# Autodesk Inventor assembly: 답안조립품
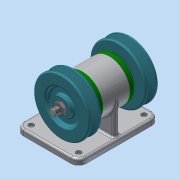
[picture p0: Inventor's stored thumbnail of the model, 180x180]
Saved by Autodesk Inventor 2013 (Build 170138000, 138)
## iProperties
Created: 2019-09
Part Number: 답안조립품
Document SubType Name: Assembly
Designer: Administrator
Author: Administrator
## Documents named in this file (10)
- C:\Users\Administrator\Desktop\490904V1028\답안조립품.iam
- C:\Users\Administrator\Desktop\490904V1028\본체.ipt
- C:\Users\Administrator\Desktop\490904V1028\V-벨트풀리.ipt
- C:\Users\Administrator\Desktop\490904V1028\너트 M10x1.ipt
- C:\Users\Administrator\Desktop\490904V1028\베어링 6004.ipt
- C:\Users\Administrator\Desktop\490904V1028\볼트 M4.ipt
- C:\Users\Administrator\Desktop\490904V1028\오일 실 17 30 5.ipt
- C:\Users\Administrator\Desktop\490904V1028\축.ipt
- C:\Users\Administrator\Desktop\490904V1028\커버.ipt
- C:\Users\Administrator\Desktop\490904V1028\키 5 x 5 x 12.ipt
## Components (2 placed, 1 different names)
1. V-벨트풀리:1 — 각도:2
2. V-벨트풀리:2 — 각도:1
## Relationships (2: Angle 2)
- 각도:1 [Angle]: V-벨트풀리:2
- 각도:2 [Angle]: V-벨트풀리:1
